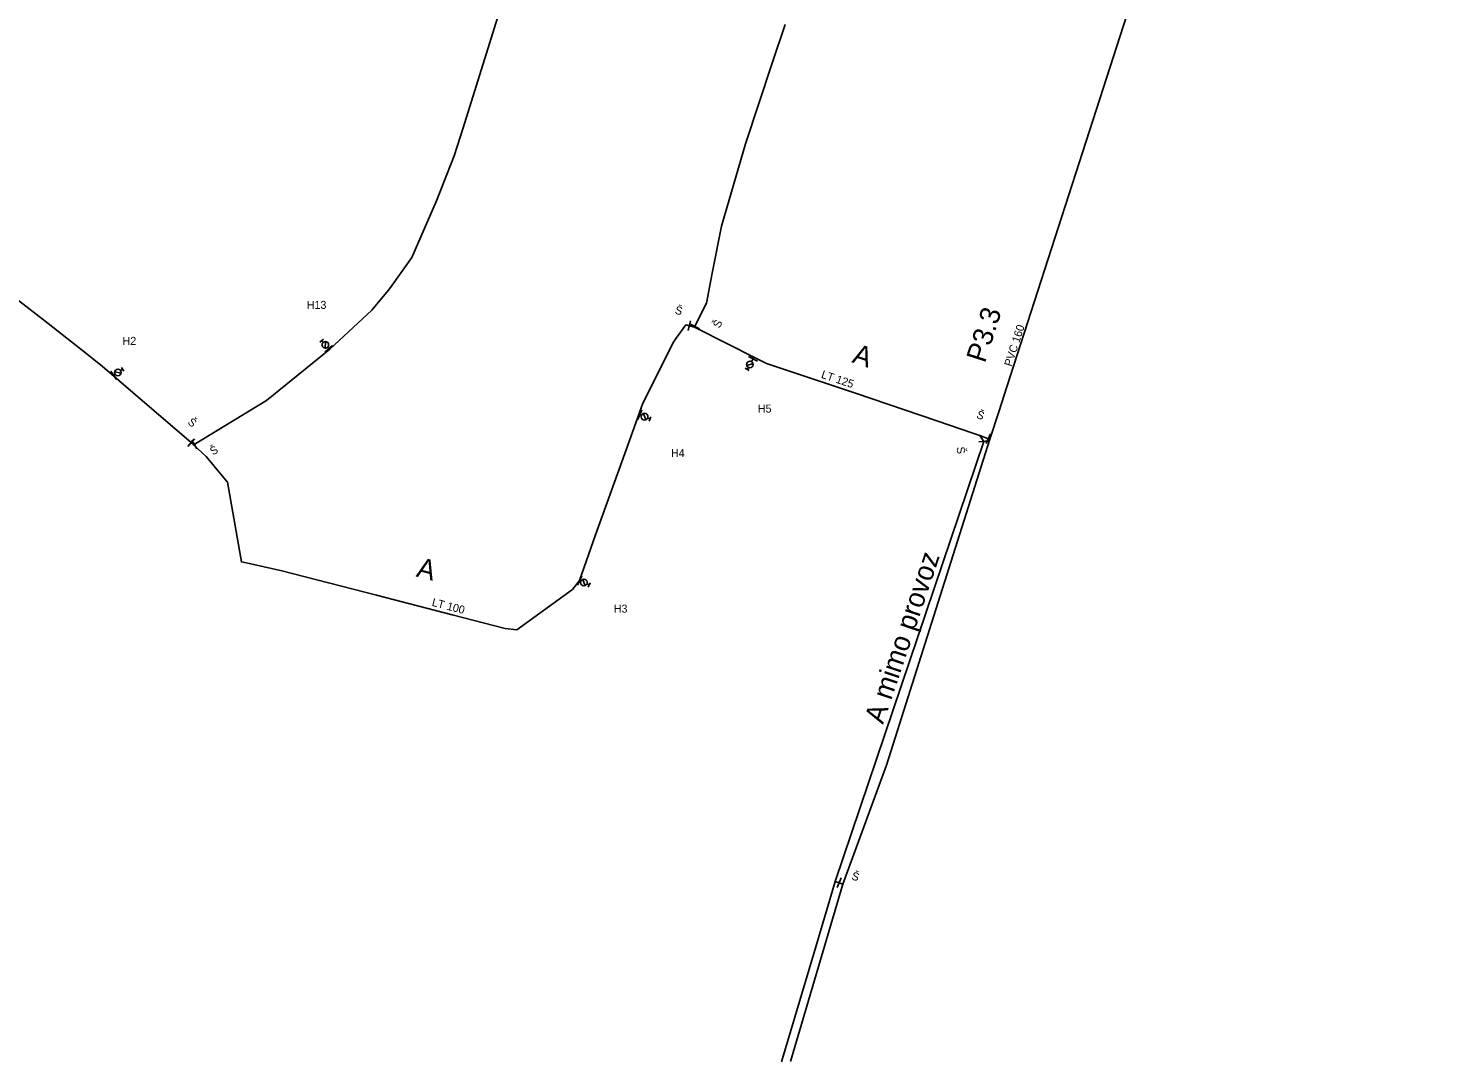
# Model space of a CAD drawing. Extents: x -574447 to -573745, y -1188179 to -1187219.
# Drawn here: x -574095.8 to -573745, y -1188178.7 to -1187920.3 of the extents above; entities that cross this region are included whole.
import ezdxf

# ---------------------------------------------------------------- set-up
doc = ezdxf.new("R2010")
doc.units = 0
for name, color, linetype in [('Vrstva 1', 7, 'Continuous'), ('Vrstva 15', 7, 'Continuous'), ('Vrstva 19', 7, 'Continuous'), ('Vrstva 25', 7, 'Continuous'), ('Vrstva 28', 7, 'Continuous'), ('Vrstva 29', 7, 'Continuous'), ('Vrstva 35', 7, 'Continuous')]:
    doc.layers.add(name, color=color, linetype=linetype)

# ---------------------------------------------------------------- blocks, each defined once
blk = doc.blocks.new('160')
at = {"layer": 'Vrstva 1'}
blk.add_circle((0, 0), 0.0458, dxfattribs=at)
blk = doc.blocks.new('147')
at = {"layer": 'Vrstva 1'}
blk.add_line((0, 1.27), (0, -1.27), dxfattribs=at)
blk = doc.blocks.new('133')
at = {"layer": 'Vrstva 1'}
for p, q in [((0.28, 0), (0, 0)), ((0.54, 0.58), (1.7, -0.58)), ((1.94, 0), (2.52, 0)), ((2.52, 0.58), (2.52, -0.58))]:
    blk.add_line(p, q, dxfattribs=at)
blk.add_circle((1.105, 0.003), 0.825, dxfattribs=at)
blk = doc.blocks.new('150')
at = {"layer": 'Vrstva 1'}
blk.add_line((0, 1.27), (0, -1.27), dxfattribs=at)

msp = doc.modelspace()

# ---------------------------------------------------------------- linework, layer by layer
at = {"layer": 'Vrstva 15'}
for p, q in [((-573929.26, -1187995.09), (-573930.569, -1187994.697)), ((-573929.164, -1187994.895), (-573929.26, -1187995.09)), ((-574054.44, -1188024.48), (-574055.102, -1188023.911)), ((-574054.44, -1188024.48), (-574054.285, -1188024.385)), ((-573894.104, -1188133.627), (-573856.99, -1188023.6)), ((-573856.99, -1188023.6), (-573857.95, -1188022.15)), ((-573857.95, -1188022.15), (-573855.815, -1188022.938)), ((-573855.815, -1188022.938), (-573855.495, -1188023.056)), ((-573893.142, -1188133.939), (-573894.104, -1188133.627)), ((-573892.18, -1188134.25), (-573893.142, -1188133.939))]:
    msp.add_line(p, q, dxfattribs=at)
for points in [[(-574054.285, -1188024.385), (-574036.2, -1188013.37), (-574020.415, -1188000.593), (-574009.94, -1187990.81), (-574005.873, -1187985.898), (-574005.27, -1187985.17), (-573999.937, -1187977.679), (-573993.761, -1187963.472), (-573989.335, -1187952.227), (-573987.085, -1187945.205), (-573973.536, -1187901.624)], [(-573906.65, -1187919.44), (-573909.867, -1187929.103), (-573916.553, -1187949.189), (-573922.52, -1187969.78), (-573924.833, -1187981.564), (-573926.31, -1187989.09), (-573927.414, -1187991.336), (-573929.164, -1187994.895)], [(-574055.102, -1188023.911), (-574068.964, -1188011.992), (-574077.3, -1188004.824), (-574082.657, -1188000.589), (-574091.983, -1187993.214), (-574098.224, -1187988.413)], [(-573930.569, -1187994.697), (-573931.46, -1187994.49), (-573933.873, -1187997.837), (-573934.56, -1187998.79), (-573942.159, -1188014.082), (-573945.6, -1188023.603), (-573954.027, -1188046.922), (-573958.03, -1188058.36), (-573959.73, -1188060.59), (-573973.72, -1188070.72), (-573976.6, -1188070.37), (-573989.84, -1188066.95), (-574008.78, -1188062.03), (-574032.448, -1188055.936), (-574039.433, -1188054.398), (-574042.51, -1188053.72), (-574045.99, -1188033.8), (-574047.314, -1188032.196), (-574051.29, -1188027.38), (-574054.44, -1188024.48)], [(-573857.95, -1188022.15), (-573859.69, -1188021.51), (-573868.717, -1188018.445), (-573889.02, -1188011.55), (-573911.31, -1188004.1), (-573914.466, -1188002.516), (-573920.665, -1187999.404), (-573929.26, -1187995.09)]]:
    msp.add_lwpolyline(points, dxfattribs=at)
at = {"layer": 'Vrstva 19'}
for points in [[(-573776.7, -1187395.74), (-573776.433, -1187397.089), (-573756.58, -1187497.42), (-573746.79, -1187550.13), (-573745, -1187653.04), (-573765.99, -1187745.82), (-573827.995, -1187937.981), (-573851.222, -1188009.966), (-573853.24, -1188016.22), (-573855.495, -1188023.056)], [(-573855.495, -1188023.056), (-573881.29, -1188104.555), (-573892.18, -1188134.25)], [(-573907.523, -1188178.705), (-573898.948, -1188149.9), (-573894.104, -1188133.627)], [(-573892.18, -1188134.25), (-573905.254, -1188178.563)]]:
    msp.add_lwpolyline(points, dxfattribs=at)
at = {"layer": 'Vrstva 25'}
for p, q in [((-574020.51, -1188000.67), (-574020.807, -1188000.33)), ((-573914.466, -1188002.516), (-573914.908, -1188003.385)), ((-574074.561, -1188007.179), (-574074.28, -1188006.99)), ((-573943.169, -1188016.878), (-573942.813, -1188016.987)), ((-573958.036, -1188058.368), (-573957.95, -1188058.399))]:
    msp.add_line(p, q, dxfattribs=at)

# ---------------------------------------------------------------- block references
for name, p, xscale, yscale, rotation in [('133', (-574020.807, -1188000.33), 0.9999999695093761, 0.9999999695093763, 131.00000134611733), ('150', (-574020.684, -1188000.47), 0.9999999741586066, 0.9999999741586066, -50.000001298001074), ('133', (-573914.908, -1188003.385), 0.9999999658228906, 0.9999999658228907, -117.99999982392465), ('150', (-573914.687, -1188002.95), 0.999999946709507, 0.999999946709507, 62.999999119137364), ('150', (-574074.42, -1188007.084), 0.9999999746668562, 0.999999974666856, 34.00000045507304), ('133', (-574074.28, -1188006.99), 0.9999999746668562, 0.999999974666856, 34.00000045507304), ('150', (-573942.95, -1188016.945), 1.0335064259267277, 1.033506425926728, -23.04128150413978), ('133', (-573942.813, -1188016.987), 1.0335064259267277, 1.033506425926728, -23.04128150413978), ('150', (-573957.993, -1188058.384), 1.0275072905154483, 1.027507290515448, -24.689105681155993), ('133', (-573957.95, -1188058.399), 1.0275072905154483, 1.027507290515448, -24.689105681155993)]:
    msp.add_blockref(name, p, dxfattribs=dict(at, xscale=xscale, yscale=yscale, rotation=rotation))
at = {"layer": 'Vrstva 29'}
for name, p, xscale, yscale, rotation in [('147', (-573930.569, -1187994.697), 0.999999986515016, 0.9999999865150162, 164.99999987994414), ('147', (-573929.164, -1187994.895), 0.999999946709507, 0.999999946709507, -117.00000088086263), ('160', (-573929.26, -1187995.09), 1.025136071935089, 1.0251360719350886, 154.74924162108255), ('147', (-574055.102, -1188023.911), 0.9999999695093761, 0.9999999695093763, 138.9999986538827), ('147', (-574054.285, -1188024.385), 0.9999999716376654, 0.9999999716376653, -150.00000103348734), ('160', (-574054.44, -1188024.48), 1.0011216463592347, 1.0011216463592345, 83.41738977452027), ('147', (-573856.99, -1188023.6), 1.0011216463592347, 1.0011216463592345, -83.41738977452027), ('160', (-573857.95, -1188022.15), 0.9999999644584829, 0.999999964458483, -39.000001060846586), ('147', (-573855.815, -1188022.938), 1.0275072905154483, 1.027507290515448, -24.689105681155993), ('160', (-573855.495, -1188023.056), 0.9999999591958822, 0.9999999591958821, 72.00000054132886), ('160', (-573894.104, -1188133.627), 0.999999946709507, 0.999999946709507, 117.00000088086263), ('147', (-573893.142, -1188133.939), 1.0335064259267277, 1.033506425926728, 156.95871849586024), ('160', (-573892.18, -1188134.25), 0.9999999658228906, 0.9999999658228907, 117.99999982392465)]:
    msp.add_blockref(name, p, dxfattribs=dict(at, xscale=xscale, yscale=yscale, rotation=rotation))

# ---------------------------------------------------------------- texts
at = {"layer": 'Vrstva 25'}
for s, p in [('H13', (-574026.177, -1187990.49)), ('H2', (-574072.21, -1187999.48)), ('H5', (-573913.458, -1188016.415)), ('H4', (-573935.163, -1188027.527)), ('H3', (-573949.45, -1188066.419))]:
    msp.add_text(s, height=2, dxfattribs=at).set_placement(p)
at = {"layer": 'Vrstva 28'}
for rotation, p in [(345.6, (-573934.309, -1187991.649)), (63.32, (-573923.021, -1187995.455)), (319.81, (-574056.113, -1188019.055)), (339.24, (-573858.993, -1188017.673)), (30.85, (-574049.63, -1188027.161)), (276.93, (-573863.802, -1188025.061)), (342.56, (-573890.192, -1188133.037))]:
    msp.add_text('Š', height=2, rotation=rotation, dxfattribs=at).set_placement(p)
at = {"layer": 'Vrstva 35'}
for s, height, rotation, p in [('P3.3', 5, 72.12, (-573856.715, -1188004.2)), ('PVC 160', 2, 72.12, (-573850.047, -1188005.024)), ('A', 5, 341.52, (-573890.132, -1188003.799)), ('LT 125', 2, 341.52, (-573897.77, -1188007.68)), ('A', 5, 345.44, (-573999.023, -1188057.329)), ('A mimo provoz', 4.99998, 71.36, (-573882.18, -1188094.462)), ('LT 100', 2, 345.44, (-573995.051, -1188064.671))]:
    msp.add_text(s, height=height, rotation=rotation, dxfattribs=at).set_placement(p)

doc.saveas('drawing.dxf')
